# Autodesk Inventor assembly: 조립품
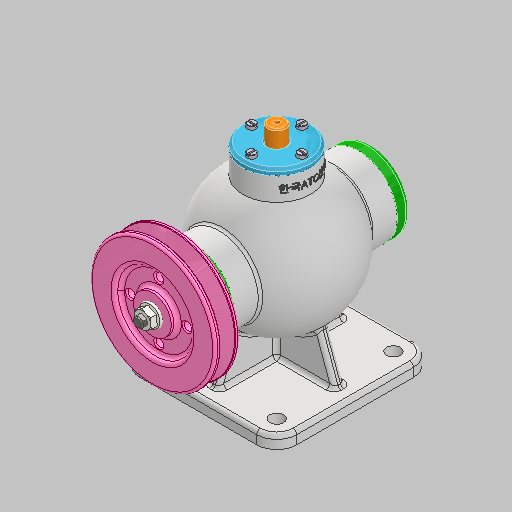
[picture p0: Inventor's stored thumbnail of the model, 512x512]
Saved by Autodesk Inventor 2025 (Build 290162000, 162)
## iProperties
Created: 2024-07
Part Number: 조립품
Document SubType Name: Assembly
Designer: 현기
Author: 현기
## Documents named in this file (15)
- C:\Users\현기\Desktop\740708V1001\조립품.iam
- C:\Users\현기\Desktop\740708V1001\본체.ipt
- C:\Users\현기\Desktop\740708V1001\V-벨트풀리\V-벨트풀리.ipt
- C:\Users\현기\Desktop\740708V1001\너트 M8\너트 M8.ipt
- C:\Users\현기\Desktop\740708V1001\뒤커버\뒤커버.ipt
- C:\Users\현기\Desktop\740708V1001\베어링- 6202\베어링- 6202.ipt
- C:\Users\현기\Desktop\740708V1001\볼트 M4 x 12\볼트 M4 x 12.ipt
- C:\Users\현기\Desktop\740708V1001\볼트 M4 x 16\볼트 M4 x 16.ipt
- C:\Users\현기\Desktop\740708V1001\상부커버\상부커버.ipt
- C:\Users\현기\Desktop\740708V1001\슬라이드\슬라이드.ipt
- C:\Users\현기\Desktop\740708V1001\앞커버\앞커버.ipt
- C:\Users\현기\Desktop\740708V1001\오일실 15 30 7\오일실 15 30 7.ipt
- C:\Users\현기\Desktop\740708V1001\칼라\칼라.ipt
- C:\Users\현기\Desktop\740708V1001\키 4 x 4 x 12\키 4 x 4 x 12.ipt
- C:\Users\현기\Desktop\740708V1001\편심축\편심축.ipt
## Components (1 placed, 1 different names)
1. V-벨트풀리:1 — 각도:4
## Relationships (1: Angle 1)
- 각도:4 [Angle]: V-벨트풀리:1
